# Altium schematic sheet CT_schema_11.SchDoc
size 274 x 160 mm
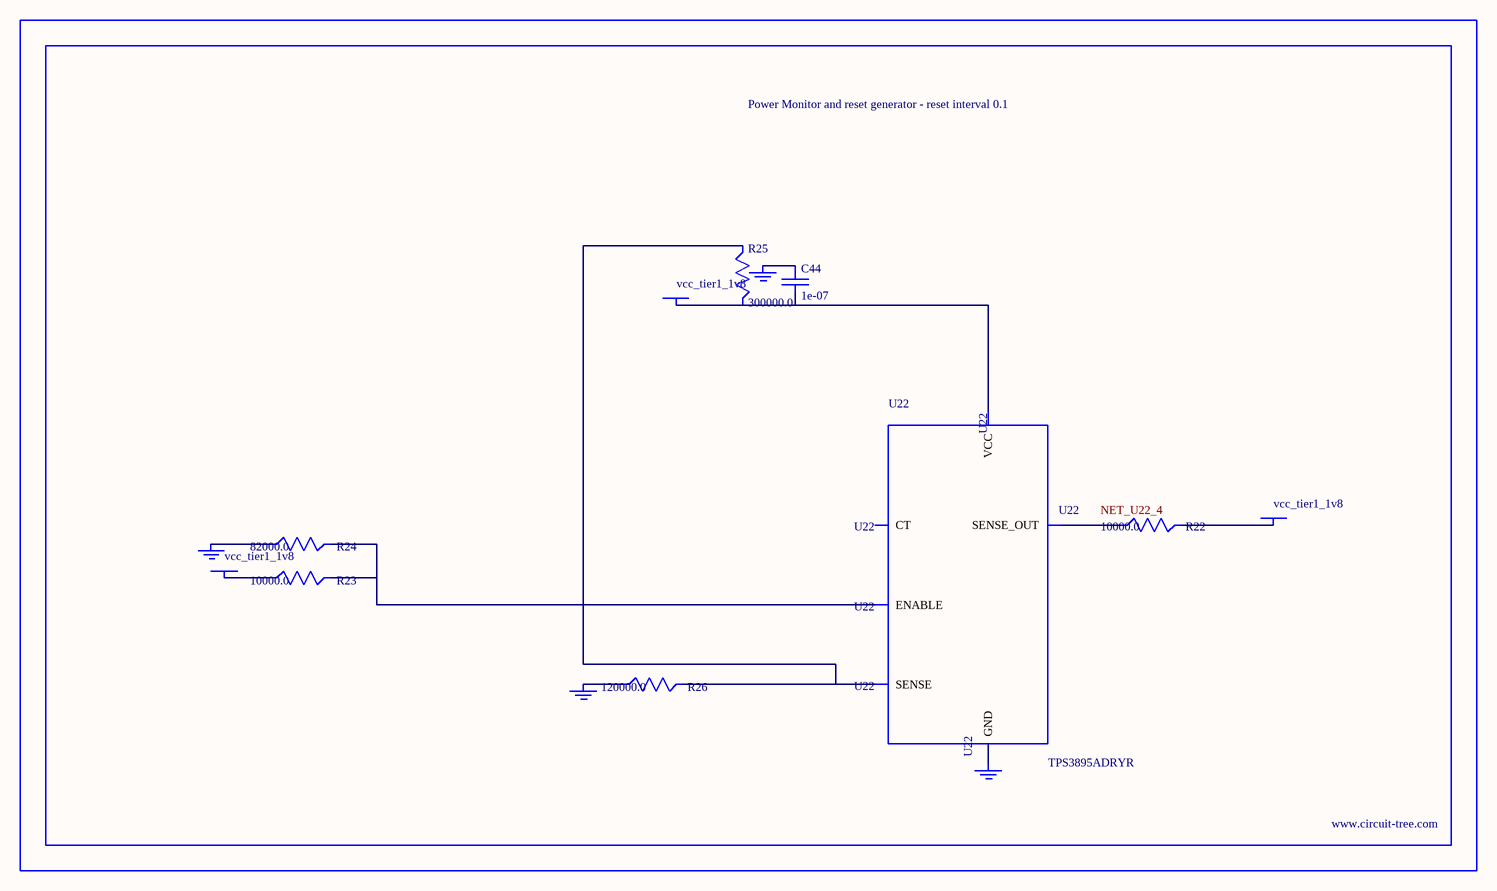
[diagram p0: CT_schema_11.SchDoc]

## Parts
BORDER10  (no value)
C44  1e-07  [C0402]
GND_INSTANCE_10_0  (no value)
GND_INSTANCE_10_1  (no value)
GND_INSTANCE_10_2  (no value)
GND_INSTANCE_10_3  (no value)
POWER_INSTANCE_10_0  vcc_tier1_1v8
POWER_INSTANCE_10_1  vcc_tier1_1v8
POWER_INSTANCE_10_2  vcc_tier1_1v8
R22  10000.0  [R0603]
R23  10000.0  [R0603]
R24  82000.0  [R0603]
R25  300000.0  [R0603]
R26  120000.0  [R0603]
U22  TPS3895ADRYR  [SON-6]

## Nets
NetC44_1: C44.1 GND_INSTANCE_10_2.0(GND)
NetC44_2: C44.2 POWER_INSTANCE_10_2.0(PWR) R25.2 U22.6(VCC)
NetGND_INSTANCE_10_0_0: GND_INSTANCE_10_0.0(GND) R24.1
NetGND_INSTANCE_10_1_0: GND_INSTANCE_10_1.0(GND) R26.1
NetGND_INSTANCE_10_3_0: GND_INSTANCE_10_3.0(GND) U22.2(GND)
NetPOWER_INSTANCE_10_0_0: POWER_INSTANCE_10_0.0(PWR) R23.1
NetPOWER_INSTANCE_10_1_0: POWER_INSTANCE_10_1.0(PWR) R22.2
NetR22_1: R22.1 U22.4(SENSE_OUT)
NetR23_2: R23.2 R24.2 U22.1(ENABLE)
NetR25_1: R25.1 R26.2 U22.3(SENSE)

Not connected (* = marked no-connect by the designer): U22 5(CT)

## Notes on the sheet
- Labels drawn without touching a wire or pin: NET_U22_4

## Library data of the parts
BORDER10 = BORDER_PAGE10
C44 = C0402C104K3RACTU
GND_INSTANCE_10_0-GND_INSTANCE_10_3 = GND
POWER_INSTANCE_10_0-POWER_INSTANCE_10_2 = PWR
R22 R23 = RC0603JR-0710KL
R24 = RC0603JR-0782KL
R25 = RC0603JR-07300KL
R26 = RC0603JR-07120KL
